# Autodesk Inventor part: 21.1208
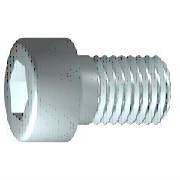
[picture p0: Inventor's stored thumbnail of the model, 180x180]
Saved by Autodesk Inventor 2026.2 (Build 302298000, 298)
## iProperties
Created: 2006-02
Part Number: 21.1208
Material: Steel, Mild
Description: M8 x 35 SHCS
Document SubType Name: Modeling
Standard: DIN 7984
Designer: Andy Moles
Standards Organization: DIN
Language: en-US
Size Designation: M8 x 35
Categories: <MemberInstance><Categories><Category DisplayName="Fasteners" InternalName="e4da775c-781d-43d5-af7c-5136215cf5a6" Mnemonic="FSTN"><Category DisplayName="Bolts"
Density: 7.85 g/cm^3
Mass: 18.1662 g
Surface Area: 13.9466 cm^2
Volume: 2.31416 cm^3
Vendor: S
Appearance: Zinc
Author: Andy Moles
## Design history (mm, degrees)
workplane "Work Plane1"
revolve "Body" stored, may be unused: angle "d10" = 90 deg
sketch "Sketch2"
  geometry: L1 (0, -9.1)-(0, 9.1) reference; L2 (-9.1, 0)-(9.1, 0) reference; L3 (2.887, 0)-(1.443, -2.5); L4 (1.443, -2.5)-(-1.443, -2.5); L5 (-1.443, -2.5)-(-2.887, 0); L6 (-2.887, 0)-(-1.443, 2.5); L7 (-1.443, 2.5)-(1.443, 2.5); L8 (1.443, 2.5)-(2.887, 0); 2 further points
  constraints: 12 end point, 1 coincident, 1 horizontal alignment, 1 point on line, 12 other
extrude "Slot" join sketch "Sketch2" stored distance "d11" = 10; taper "d12" = 0 deg
body "Solid1"
fillet "Fillet1" dims "d17" = 0.8 (= RR)
feature "Thread" dims "d13" = 22 (= GEL), "d14" = 0
chamfer "Chamfer1" distance "d15" = 0.76681 (= -0.5 x SPD + 0.5 x GD); stored, may be unused: second distance "d16" = 0.76681 (= GUL), angle "d27" = 45 deg
sketch "Sketch1"
  geometry: L1 (0.467, 0)-(35, 0); L2 (35, 0)-(35, 4); L3 (35, 4)-(13, 4); L4 (13, 4)-(12.233, 4); L5 (12.233, 4)-(0, 4); L6 (0, 4)-(0, 6.5); L7 (0, 6.5)-(-5, 6.5); L8 (-5, 6.5)-(-5, 2.887); L9 (-5, 2.887)-(-1.2, 2.887); L10 (-1.2, 2.887)-(0.467, 0); L11 (-13, 0)-(43, 0) reference; L12 (0, -1.3)-(0, 7.8) reference; L13 (13, 4)-(0, 4)
  constraints: 22 end point, 6 parallel, 2 collinear, 2 perpendicular, 1 horizontal, 1 point on line
  dimensions: "d1" = 22 distance from line of L3.end L2 (= GEL); "d2" = 0.76691 distance of L4.end L3.end (computed from GAL); "d3" = 5 distance between parallel lines of L8 L6 (= KOH); "d4" = 3.8 distance of L8.end L9.end (= INTI); "d5" = 60 deg angle of L10 L1; "d6" = 8 diameter of L3 L1 (= GD); "d7" = 8 diameter of L5 L1 (= BDM); "d8" = 5.7735 diameter of L9 L1 (= 1.1547 x SW); "d9" = 13 diameter of L7 L1 (= KOD); "d26" = 35 distance between parallel lines of L12 L2 (= NLG)
other parameters: "GD" = 8 (= NND) [user parameter; used in 2 equation terms], "NLG" = 35 [user parameter; used in 1 equation term], "GEL" = 22 [user parameter; used in 2 equation terms], "KOD" = 13 [user parameter; used in 1 equation term], "KOH" = 5 [user parameter; used in 1 equation term], "INTI" = 3.8 [user parameter; used in 1 equation term], "GAL" = 0.76681 (= 0.61345 x PTC) [user parameter; used in 1 equation term], "GUL" = 0.76681 (= 0.61345 x PTC) [user parameter; used in 1 equation term], "BDM" = 8 (= NND) [user parameter; used in 1 equation term], "SW" = 5 [user parameter; used in 2 equation terms], "RR" = 0.8 [user parameter; used in 1 equation term], "SPD" = 6.46637 (= NND - 1.2269 x PTC) [user parameter; used in 1 equation term], "d19" = 0, "d28" = 0, "d29" = 0, "TOA" = 30 deg [user parameter], "GD1" = 6.46637 (= THREADDIA - 1.2269 x PTC) [user parameter], "THREADDIA" = 8 [user parameter; used in 1 equation term], "FAWI" = 45 deg [user parameter], "ANG" = 120 deg [user parameter], "TPU" = 8 (computed from PTC) [user parameter], "PTC" = 1.25 [user parameter; used in 5 equation terms], "NND" = 8 [user parameter; used in 3 equation terms], "E0" = 5.775 (= 1.155 x SW) [user parameter]
